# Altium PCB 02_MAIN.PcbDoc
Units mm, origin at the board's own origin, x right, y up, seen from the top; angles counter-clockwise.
Board outline 20 x 20.01 mm, 2 copper layers (Top Layer, Bottom Layer), stack 0.871 mm thick; 12 components, 32 nets, 87 pads, 62 vias.
Unrouted connection lines stored in the file: 7.
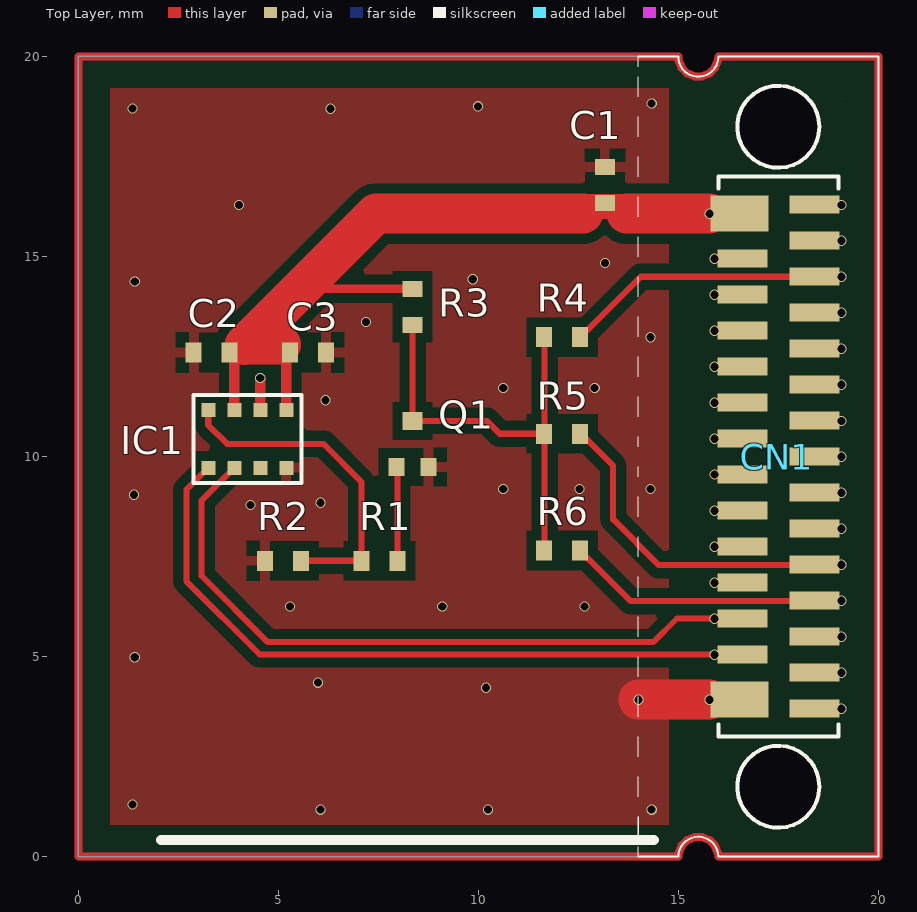
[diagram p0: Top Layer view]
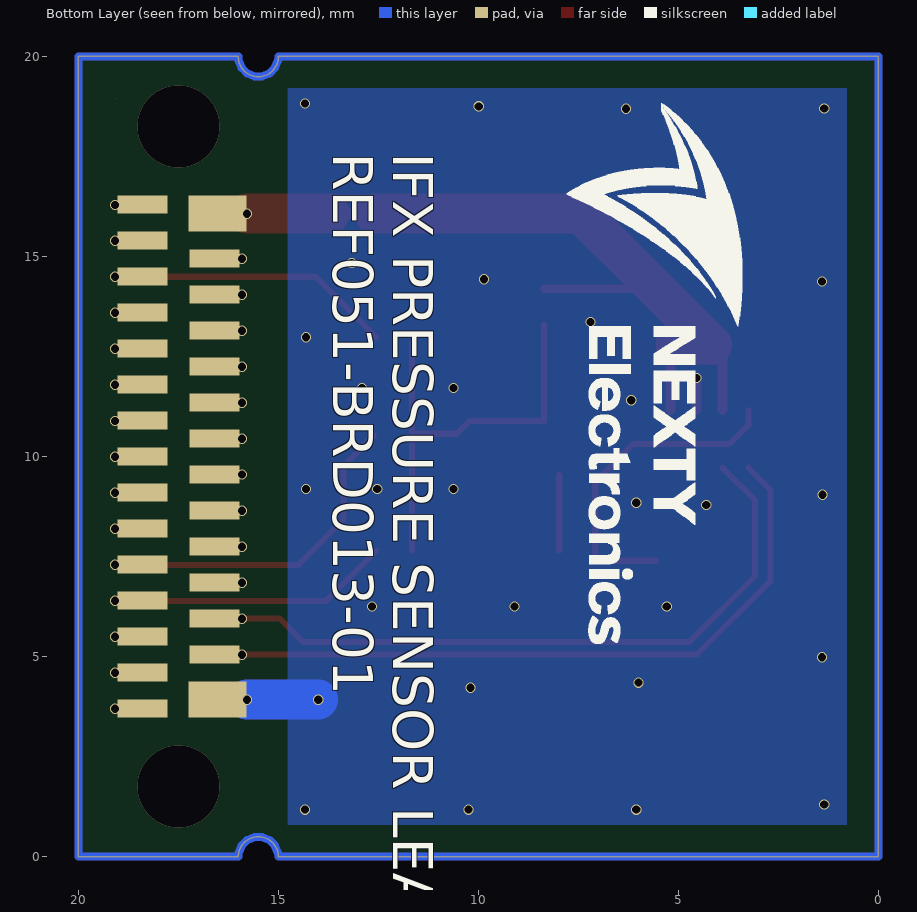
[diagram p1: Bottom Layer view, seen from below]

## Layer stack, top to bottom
Top Solder: solder mask 0.0102, Solder Resist, Dk 3.5
Top Layer: signal copper 0.0356
Dielectric 1: dielectric 0.8, FR-4, Dk 4.8
Bottom Layer: signal copper 0.0356
Bottom Solder: solder mask 0.0102, Solder Resist, Dk 3.5

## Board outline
0,0 0,20.01 15,20.01 15,20 ccw(c15.5,20) 16,20 16,20.01 20,20.01 20,0 16,0 ccw(c15.5,0) 15,0
cut-out: 19.083,18.956

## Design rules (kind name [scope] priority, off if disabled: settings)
Clearance [All] p1: gap=0.254 ignorepadtopadclearanceinfootprint=FALSE except(0: Arc-Hole Track-Hole SMDPad-Hole THPad-Hole Via-Hole Fill-Hole Poly-Hole Region-Hole Text-Hole)
PolygonConnect PolygonConnect_1 [All] p1: thpad.connectstyle=Direct thpad.reliefconductorwidth=0.254 thpad.reliefentries=4 thpad.polygonreliefangle="90 Angle" thpad.airgapwidth=0.254 smdpad.connectstyle=Relief smdpad.reliefconductorwidth=0.254 smdpad.reliefentries=4 smdpad.polygonreliefangle="90 Angle" smdpad.airgapwidth=0.254 via.connectstyle=Direct via.reliefconductorwidth=0.254 via.reliefentries=4 via.polygonreliefangle="90 Angle" via.airgapwidth=0.254
RoutingVias [All] p1: holewidth=0.711 width=1.27 viastyle="Through Hole" minholewidth=0.203 minwidth=0.254 maxholewidth=0.711 maxwidth=1.27
SolderMaskExpansion [All] p1: expansion=0.102 istentingtop=FALSE
Width [All] p1: maxlimit=0.254 minlimit=0.203 preferedwidth=0.203 minimp=50.000000 maximp=50.000000 favimp=50.000000
30 further rules are at their usual default settings.

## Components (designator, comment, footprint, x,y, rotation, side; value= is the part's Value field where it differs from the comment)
C1 "0.1u" C-1005 13.163,16.797 r90 top
C2 "0.1u" C-1005 3.335,12.606 r180 top
C3 "0.1u" C-1005 5.748,12.606 r0 top
CN1 "Leaf IF Pad" LEAF_PAD_REV2 17.5,10 r0 top locked
IC1 "DPS310" PG-VLGA-8 4.224,10.447 r180 top
Q1 "SSM3K15AMFV" SOT-723 8.357,10.32 r0 top
R1 "47" R-1005 7.526,7.399 r0 top
R2 "100k(未実装)" R-1005 5.113,7.399 r180 top
R3 "100k" R-1005 8.357,13.749 r270 top
R4 "0(未実装)" R-1005 12.098,12.987 r0 top
R5 "0(未実装)" R-1005 12.098,10.574 r0 top
R6 "0" R-1005 12.098,7.653 r0 top

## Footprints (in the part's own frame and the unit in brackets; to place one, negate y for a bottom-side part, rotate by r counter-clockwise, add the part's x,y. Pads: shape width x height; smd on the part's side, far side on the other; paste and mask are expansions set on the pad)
C-1005 [mm]
  rect 0.4x0.5 smd: 1(-0.45,0) 2(0.45,0)
LEAF_PAD_REV2 [mm]
  rect 1.45x0.9 smd far side paste-1: B1(-0.975,6.075) B27(-0.975,-6.075)
  rect 1.25x0.45 smd far side paste-1: B2(0.9,6.3) B3(-0.9,4.95) B4(0.9,5.4) B5(-0.9,4.05) B6(0.9,4.5) B7(-0.9,3.15) B8(0.9,3.6) B9(-0.9,2.25) B10(0.9,2.7) B11(-0.9,1.35) B12(0.9,1.8) B13(-0.9,0.45) B14(0.9,0.9) B15(-0.9,-0.45) B16(0.9,0) B17(-0.9,-1.35) B18(0.9,-0.9) B19(-0.9,-2.25) B20(0.9,-1.8) B21(-0.9,-3.15) B22(0.9,-2.7) B23(-0.9,-4.05) B24(0.9,-3.6) B25(-0.9,-4.95) B26(0.9,-4.5) B28(0.9,-5.4) B29(0.9,-6.3)
  rect 1.45x0.9 smd paste-1: F1(-0.975,6.075) F27(-0.975,-6.075)
  rect 1.25x0.45 smd paste-1: F2(0.9,6.3) F3(-0.9,4.95) F4(0.9,5.4) F5(-0.9,4.05) F6(0.9,4.5) F7(-0.9,3.15) F8(0.9,3.6) F9(-0.9,2.25) F10(0.9,2.7) F11(-0.9,1.35) F12(0.9,1.8) F13(-0.9,0.45) F14(0.9,0.9) F15(-0.9,-0.45) F16(0.9,0) F17(-0.9,-1.35) F18(0.9,-0.9) F19(-0.9,-2.25) F20(0.9,-1.8) F21(-0.9,-3.15) F22(0.9,-2.7) F23(-0.9,-4.05) F24(0.9,-3.6) F25(-0.9,-4.95) F26(0.9,-4.5) F28(0.9,-5.4) F29(0.9,-6.3)
  silkscreen extent -3.5,-10 2.5,10
PG-VLGA-8 [mm]
  rect 0.35x0.35 smd: 1(-0.975,0.725) 2(-0.325,0.725) 3(0.325,0.725) 4(0.975,0.725) 5(0.975,-0.725) 6(0.325,-0.725) 7(-0.325,-0.725) 8(-0.975,-0.725)
  silkscreen extent -1.35,-1.1 1.35,1.1
R-1005 [mm]
  rect 0.4x0.5 smd: 1(-0.45,0) 2(0.45,0)
SOT-723 [mm]
  rect 0.4x0.45 smd: 1(-0.4,-0.575) 2(0.4,-0.575)
  rect 0.5x0.45 smd: 3(0,0.575)

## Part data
C1 C2 C3: library part C
CN1: library part Leaf_IF_Pad2
IC1: library part IFX@DPS310
Q1: library part TOSHIBA@SSM3K15AMFV
R1 R2 R3 R4 R5 R6: library part R_chip

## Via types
v1: diameter 0.254, hole 0.203, Top Layer to Bottom Layer, 60 vias
v2: diameter 2.05, hole 2.05, Top Layer to Bottom Layer, 2 vias

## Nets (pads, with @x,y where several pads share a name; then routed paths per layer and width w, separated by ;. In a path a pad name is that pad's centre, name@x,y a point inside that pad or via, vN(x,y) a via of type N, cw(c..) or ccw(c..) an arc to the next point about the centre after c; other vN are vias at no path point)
GND: C1.2 C2.2 C3.2 CN1.B27 CN1.F27 IC1.1 IC1.7 Q1.2 R2.2 | length 4.4
  Top Layer w0.254: IC1.7 v1(4.549,11.971)
  Top Layer w1: v1(14.003,3.925) v1(15.781,3.925)
  Bottom Layer w1: v1(14.003,3.925) v1(15.781,3.925)
  other v1: 6.051,1.176 10.242,1.176 14.334,1.176 1.352,1.303 10.194,4.224 5.993,4.351 1.41,4.986 5.289,6.256 9.099,6.256 12.655,6.256 4.301,8.796 6.051,8.848 1.393,9.05 10.623,9.189 12.528,9.189 14.306,9.189 6.178,11.411 10.623,11.717 12.909,11.717 14.306,12.987 7.195,13.364 1.41,14.384 9.861,14.436 13.163,14.839 4.019,16.289 1.352,18.702 6.305,18.698 9.988,18.76 14.334,18.829
INT0: CN1.B22 CN1.F22 R5.2 | length 7.4
  Top Layer w0.152: R5.2@12.611,10.535 13.368,9.778 13.368,8.432 14.511,7.289 CN1.F22@17.892,7.289
  other v1: 19.083,7.3
INT1: CN1.B24 CN1.F24 R6.2 | length 5.9
  Top Layer w0.152: R6.2 13.812,6.389 CN1.F24@17.892,6.389
  other v1: 19.083,6.4
INT2: CN1.B6 CN1.F6 R4.2 | length 6.5
  Top Layer w0.152: R4.2 14.061,14.5 CN1.F6
  other v1: 19.083,14.5
NetCN1_B2: CN1.B2 CN1.F2
  other v1: 19.083,16.289
NetCN1_B3: CN1.B3 CN1.F3
  other v1: 15.908,14.95
NetCN1_B4: CN1.B4 CN1.F4
  other v1: 19.083,15.4
NetCN1_B5: CN1.B5 CN1.F5
  other v1: 15.908,14.05
NetCN1_B7: CN1.B7 CN1.F7
  other v1: 15.908,13.15
NetCN1_B8: CN1.B8 CN1.F8
  other v1: 19.083,13.6
NetCN1_B9: CN1.B9 CN1.F9
  other v1: 15.908,12.25
NetCN1_B10: CN1.B10 CN1.F10
  other v1: 19.083,12.7
NetCN1_B11: CN1.B11 CN1.F11
  other v1: 15.908,11.35
NetCN1_B12: CN1.B12 CN1.F12
  other v1: 19.083,11.8
NetCN1_B13: CN1.B13 CN1.F13
  other v1: 15.908,10.45
NetCN1_B14: CN1.B14 CN1.F14
  other v1: 19.083,10.895
NetCN1_B15: CN1.B15 CN1.F15
  other v1: 15.908,9.558
NetCN1_B16: CN1.B16 CN1.F16
  other v1: 19.083,10
NetCN1_B17: CN1.B17 CN1.F17
  other v1: 15.908,8.65
NetCN1_B18: CN1.B18 CN1.F18
  other v1: 19.083,9.1
NetCN1_B19: CN1.B19 CN1.F19
  other v1: 15.908,7.75
NetCN1_B20: CN1.B20 CN1.F20
  other v1: 19.083,8.2
NetCN1_B21: CN1.B21 CN1.F21
  other v1: 15.908,6.85
NetCN1_B26: CN1.B26 CN1.F26
  other v1: 19.083,5.5
NetCN1_B28: CN1.B28 CN1.F28
  other v1: 19.083,4.6
NetCN1_B29: CN1.B29 CN1.F29
  other v1: 19.083,3.7
NetIC1_5: IC1.5 R1.1 R2.1 | length 8.3
  Top Layer w0.152: IC1.5 3.249,10.79 3.719,10.32 6.129,10.32 7.076,9.373 R1.1 R2.1
NetQ1_1: Q1.1 R1.2 | length 1.9
  Top Layer w0.152: 7.976,7.653 Q1.1@7.976,9.542
NetQ1_3: Q1.3 R3.2 R4.1 R5.1 R6.1 | length 11
  Top Layer w0.152: R3.2 Q1.3 10.215,10.895 10.536,10.574 R5.1 ; R6.1@11.659,7.653 11.659,10.574 R4.1@11.659,12.844
SCL: CN1.B25 CN1.F25 IC1.4 | length 17
  Top Layer w0.152: IC1.4@3.249,9.725 IC1.4 2.7,9.176 2.7,6.891 4.535,5.056 v1@15.86,5.056
  other v1: 15.908,5.05
SDA: CN1.B23 CN1.F23 IC1.3 | length 16.8
  Top Layer w0.152: IC1.3@3.899,9.725 3.081,8.907 3.081,7.018 4.732,5.367 14.378,5.367 14.967,5.956 v1@15.86,5.956
  other v1: 15.908,5.95
VCC_3V3: C1.1 C2.1 C3.1 CN1.B1 CN1.F1 IC1.6 IC1.8 R3.1 | length 20.6
  Top Layer w0.203: C2.1@3.899,12.606 C2.1@3.912,12.606 ; C3.1@5.199,12.606 C3.1 ; 5.846,14.482 5.846,14.199 R3.1 ; 12.686,16.47 13.667,16.47
  Top Layer w0.254: IC1.6 C2.1@3.899,12.606 ; IC1.8 C3.1@5.199,12.606 ; 12.611,16.075 13.705,16.075
  Top Layer w1: 4.16,12.796 5.846,14.482 7.439,16.075 12.611,16.075 ; 4.236,12.8 5.072,12.8 ; 13.705,16.075 v1(15.781,16.075)
pads on no net: IC1.2
copper on no net:
  other v2: 17.5,1.75 17.5,18.25

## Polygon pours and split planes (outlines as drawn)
GND on Bottom Layer "GND_L02_P012" (solid, pour order 12): 0.795,19.21 14.765,19.21 14.765,0.795 0.795,0.795
GND on Top Layer "GND_L01_P016" (solid, pour order 16): 14.765,0.795 14.765,19.21 0.795,19.21 0.795,0.795

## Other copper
Multi-Layer:
  lines w0.2: 0,0 15,0 15.01,0.098 15.084,0.278 15.222,0.416 15.402,0.49 15.598,0.49 15.778,0.416 15.916,0.278 15.99,0.098 16,0 20,0 20,20.01 16,20.01 15.99,19.902 15.916,19.722 15.778,19.584 15.598,19.51 15.402,19.51 15.222,19.584 15.084,19.722 15.01,19.902 15,20 0,20.01 0,0

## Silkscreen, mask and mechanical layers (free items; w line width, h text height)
Top Overlay:
  lines w0.254: 2.065,0.414 14.384,0.414
Bottom Overlay:
  drawing of 2311 lines, arcs and shapes, not listed
  text "IFX PRESSURE SENSOR LEAF / REF051-BRD013-01" at 13.622,17.594 h1 r90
